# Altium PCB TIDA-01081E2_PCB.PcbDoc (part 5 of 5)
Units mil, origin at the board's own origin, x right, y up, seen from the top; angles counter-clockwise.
Board outline 8611.33 x 3169.64 mil, 4 copper layers (Top Layer, VCC, GND, Bottom Layer), stack 61.6 mil thick; 411 components, 187 nets, 1087 pads, 1987 vias.
Unrouted connection lines stored in the file: 7.
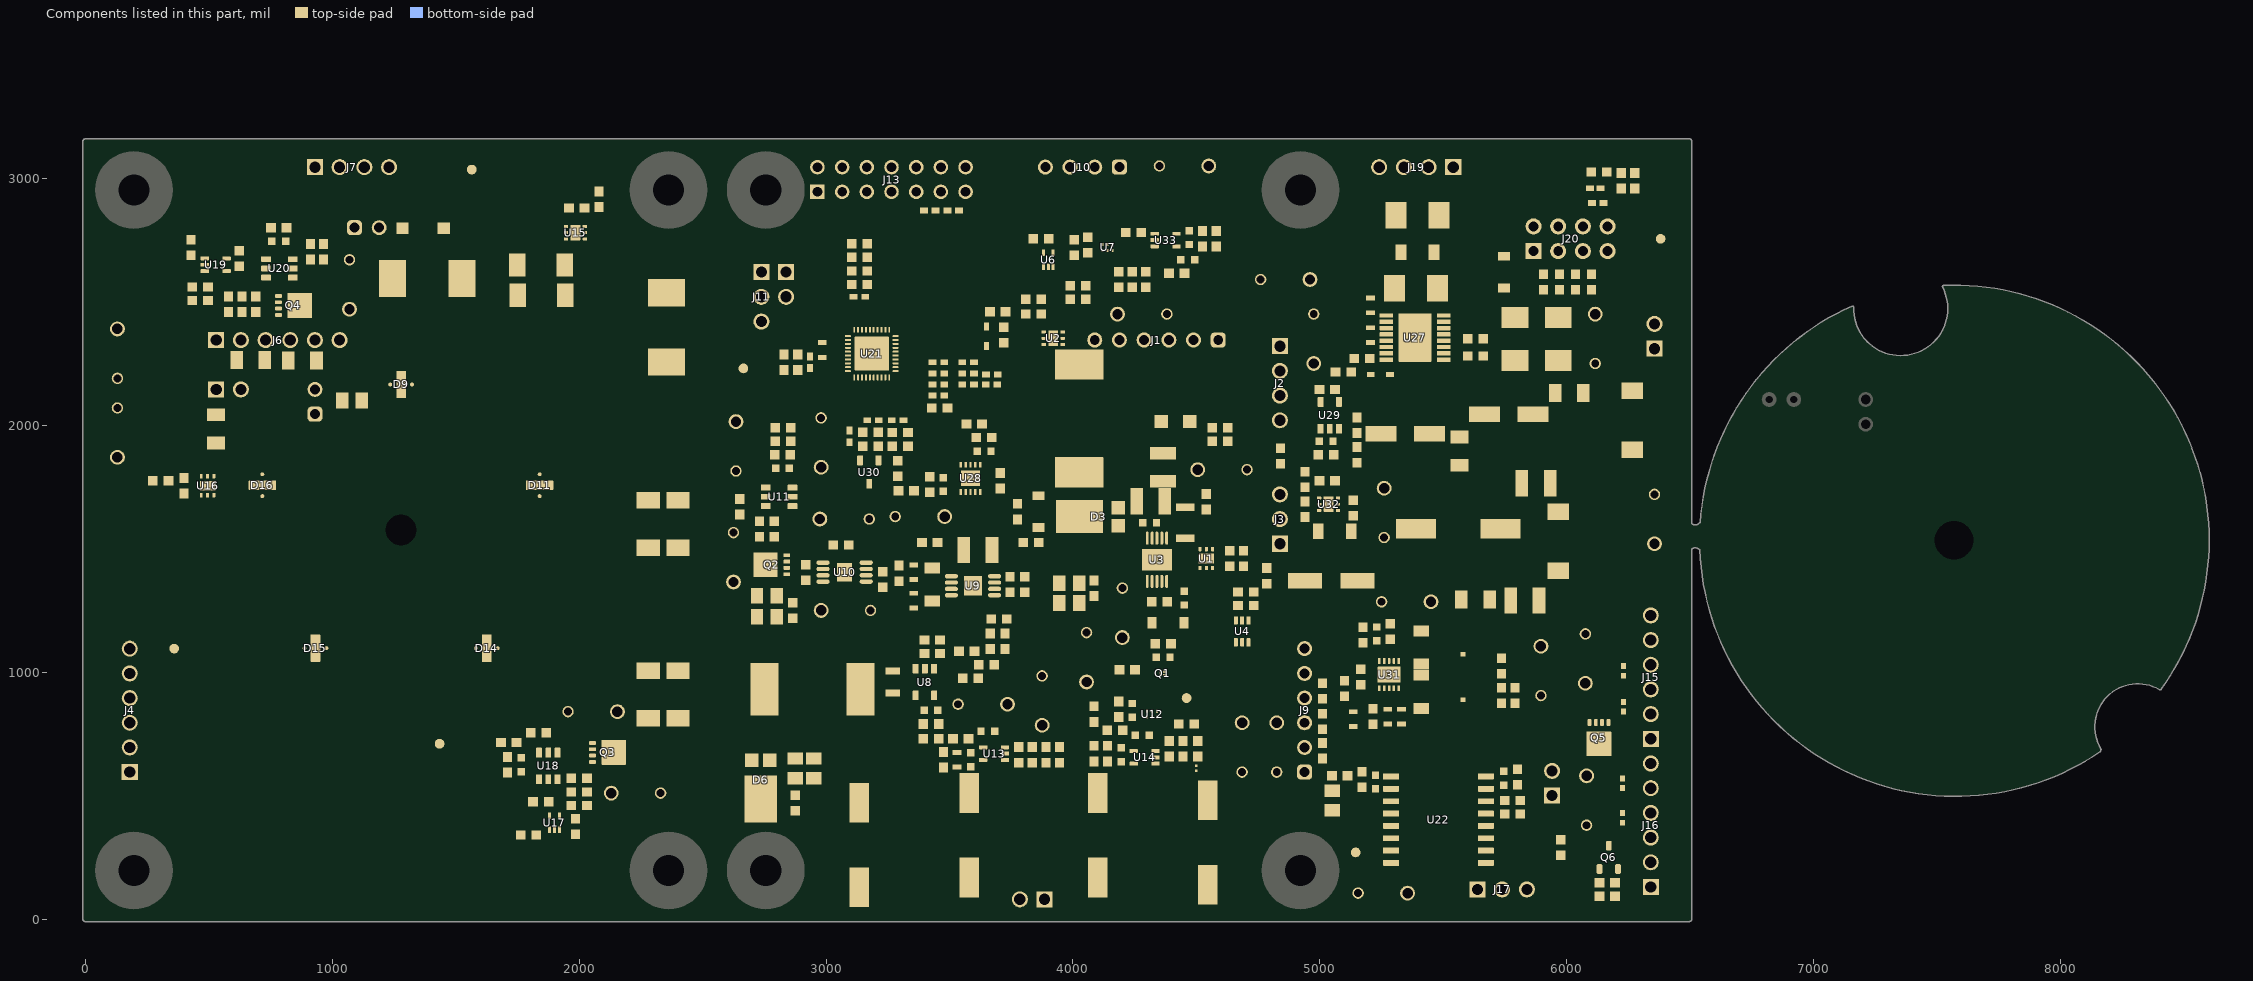
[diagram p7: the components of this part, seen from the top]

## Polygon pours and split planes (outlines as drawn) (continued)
+5V0 on Top Layer "TOP_LAYER_+5V0_P474" (solid, remove dead copper, pour order 474): 690,2850 785,2850 785,2775 690,2775
GND on Top Layer "TOP_LAYER_GND_P476" (solid, remove dead copper, pour order 476): 4221.3,2580 4315,2580 4315,2490 4220,2490
GND on Top Layer "TOP_LAYER_GND_P478" (solid, remove dead copper, pour order 478): 795,2860 795,2780 868.16,2780 875,2786.84 875,2860
+5V0 on Top Layer "TOP_LAYER_+5V0_P480" (solid, remove dead copper, pour order 480): 580,2720 580,2785 670,2785 670,2720
GND_ISO on Top Layer "TOP_LAYER_GND_ISO_P482" (solid, remove dead copper, pour order 482): 6110,775 6110,840 6180,840 6180,775
NetC73_1 on Top Layer "TOP_LAYER_NETC73_1_P484" (solid, remove dead copper, pour order 484): 5720,2665 5805,2665 5805,2765 5720,2765
NetD9_1 on Top Layer "TOP_LAYER_NETD9_1_P486" (solid, remove dead copper, pour order 486): 1160,2140 1160,1920 1050,1920 1050,2120 1070,2140
BUCK_VOUT on VCC "VCC_BUCK_VOUT_P428" (solid, remove dead copper, pour order 428): 4325,2150 4324.8,2150.2 4324.8,2398.9 3773.9,2398.9 3769.09,2394.09 3769.09,2150
NetQ3_5 on VCC "VCC_NETQ3_5_P356" (solid, remove dead copper, pour order 356): 2080,780 2080,560 2530,560 2530,900 2210,900 2210,780
NetR133_1 on VCC "VCC_NETR133_1_P350" (solid, remove dead copper, pour order 350): 2210,900 2530,900 2530,1600 2210,1600
NetD10_1 on VCC "VCC_NETD10_1_P344" (solid, remove dead copper, pour order 344): 2209,2375 2209,1601 2210,1600 2530,1600 2530,2375
NetD10_2 on VCC "VCC_NETD10_2_P334" (solid, remove dead copper, pour order 334): 1850,2375 2530,2375 2530,3100 1850,3100
NetD7_1 on VCC "VCC_NETD7_1_P326" (solid, remove dead copper, pour order 326): 1285,2375 1850,2375 1850,3100 1285,3100 1285,2375
NetC95_1 on VCC "VCC_NETC95_1_P316" (solid, remove dead copper, pour order 316): 979,2160.2 1168.8,2160.2 1170,2850 990,2850 990,2560 790,2560 790,2220.8 789.2,2220 979,2220
NetD9_1 on VCC "VCC_NETD9_1_P235" (solid, remove dead copper, pour order 235): 1179,2245 1249.79,2245 1254,2240.79 1254,1875 1179,1875 1179,2150
NetD9_2 on VCC "VCC_NETD9_2_P239" (solid, remove dead copper, pour order 239): 1789,1790 1894,1790 1894,1945 2090,1945 ccw(c2090,2064) 2209,2064 2209,2296 ccw(c2130,2296) 2130,2375 1255,2375 ccw(c1255,2304) 1184,2304 1184,1945 1184,1916 ccw(c1280,1916) 1280,1820 1384,1820 1384,1945 1789,1945
NetD11_2 on VCC "VCC_NETD11_2_P245" (solid, remove dead copper, pour order 245): 1659,1045 1857.83,1045 1859,1043.83 1859,861 ccw(c1925,861) 1925,795 2140,795 ccw(c2140,864) 2209,864 2209,1866 ccw(c2130,1866) 2130,1945 1394,1945 1394,1821.83 1550,1520 1789,1520 1859,1520 1859,1150.17 1659.17,1150.17
NetD14_2 on VCC "VCC_NETD14_2_P247" (solid, remove dead copper, pour order 247): 1859,1520 1859,795 1178.81,795 1178.81,895.45 1178.81,1043.83 970.17,1043.83 964,1050 964,1150 1178.64,1150 1178.81,1320 1430,1345 1548.64,1520
NetD15_2 on VCC "VCC_NETD15_2_P252" (solid, remove dead copper, pour order 252): 641,1730.41 789.79,1730.41 789.79,1520.41 813.57,1520.41 871,1520.41 951,1520.41 1025,1520.41 1178.81,1325.6 1178.81,1189.81 1178.81,795 479,795 479,1520.41 636,1520.41 638.21,1522.63 638.21,1730.41
NetD16_2 on VCC "VCC_NETD16_2_P256" (solid, remove dead copper, pour order 256): 479,1995 1174,1995 1174,1825 1050,1710 1019,1525 479,1525
NetD6_1 on VCC "VCC_NETD6_1_P370" (solid, remove dead copper, pour order 370): 2590,1491.53 2820,1491.53 2820,485 2590,485
+5V0 on VCC "VCC_+5V0_P362" (solid, remove dead copper, pour order 362): 1285,3100 1285,2400 465,2400 465,780 2530,780 2530,310 1010,310 63.69,310 50.85,322.83 50,323.69 50,3100
NetC4_1 on VCC "VCC_NETC4_1_P416" (solid, remove dead copper, pour order 416): 3920,1325 3920,1195 3930,1185 4462.35,1185 4482.35,1205 4482.35,1389.03 4462.35,1409.03 4307.07,1409.03 4295,1396.96 4295,1345 4285,1335 3930,1335
NetC4_1 on VCC "VCC_NETC4_1_P456" (solid, remove dead copper, pour order 456): 3924.71,1851.04 3926.88,1853.21 4120.26,1853.21 4120.26,1570.26 4060,1510 4060,1411.5 3903.5,1411.5 3900,1415 3900,1807.07
BOOST_VOUT/BUCK_VIN on VCC "VCC_BOOST_VOUT/BUCK_VIN_P472" (solid, remove dead copper, pour order 472): 4420,1830 4480,1830 4480,1700 4420,1700
GND_ISO on GND "GND_GND_ISO_P426" (solid, remove dead copper, pour order 426): 5600,50 5605,55 5605,560 5700,655 5975,655 6061.75,741.75 6061.75,1166.75 6175,1280 6440,1280 6440,50
GND on GND "GND_GND_P374" (solid, remove dead copper, pour order 374): 5150,2230 5756.5,2230 5756.5,2350 6446.46,2350 6446.46,1430 5865,1430 5865,798.63 5435,798.63 5435,50 2590,50 2590,3100 5150,3100
NetQ3_5 on GND "GND_NETQ3_5_P358" (solid, remove dead copper, pour order 358): 2080,780 2080,560 2530,560 2530,900 2210,900 2210,780
NetR133_1 on GND "GND_NETR133_1_P352" (solid, remove dead copper, pour order 352): 2210,900 2530,900 2530,1600 2210,1600
NetD10_1 on GND "GND_NETD10_1_P346" (solid, remove dead copper, pour order 346): 2209,2375 2209,1601 2210,1600 2530,1600 2530,2375
NetD10_2 on GND "GND_NETD10_2_P336" (solid, remove dead copper, pour order 336): 1850,2375 2530,2375 2530,3100 1850,3100
NetD7_1 on GND "GND_NETD7_1_P328" (solid, remove dead copper, pour order 328): 1285,2375 1850,2375 1850,3100 1285,3100 1285,2375
NetC95_1 on GND "GND_NETC95_1_P320" (solid, remove dead copper, pour order 320): 979,2160.2 1170,2160.2 1170,2850 990,2850 990,2560 790,2560 790,2220.8 789.2,2220 979,2220
NetD9_1 on GND "GND_NETD9_1_P237" (solid, remove dead copper, pour order 237): 1179,2245 1249.79,2245 1254,2240.79 1254,1875 1179,1875 1179,2150
NetD9_2 on GND "GND_NETD9_2_P241" (solid, remove dead copper, pour order 241): 1789,1790 1894,1790 1894,1945 2100,1945 ccw(c2100,2054) 2209,2054 2209,2248 ccw(c2150.5,2242.5) 2145,2301 1240,2301 ccw(c1238.5,2246.5) 1184,2248 1184,1945 1184,1820 1384,1820 1384,1945 1789,1945
NetD11_2 on GND "GND_NETD11_2_P244" (solid, remove dead copper, pour order 244): 1659,1045 1857.83,1045 1859,1043.83 1859,861 ccw(c1925,861) 1925,795 2140,795 ccw(c2140,864) 2209,864 2209,1866 ccw(c2130,1866) 2130,1945 1394,1945 1394,1820 1540,1520 1789,1520 1859,1520 1859,1150.17 1659.17,1150.17
NetD14_2 on GND "GND_NETD14_2_P249" (solid, remove dead copper, pour order 249): 1859,1520 1859,795 1178.81,795 1178.81,895.45 1178.81,1043.83 970.17,1043.83 964,1050 964,1150 1178.64,1150 1178.81,1325 1445,1360 1540,1520
NetD15_2 on GND "GND_NETD15_2_P253" (solid, remove dead copper, pour order 253): 641,1730.41 789.79,1730.41 789.79,1520.41 813.57,1520.41 871,1520.41 951,1520.41 1025,1522.63 1178.81,1325 1178.81,1189.81 1178.81,795 479,795 479,1520.41 636,1520.41 638.21,1522.63 638.21,1730.41
NetD16_2 on GND "GND_NETD16_2_P257" (solid, remove dead copper, pour order 257): 479,1995 1174,1995 1174,1825 1050,1715 1015,1525 479,1525
NetC73_1 on GND "GND_NETC73_1_P368" (solid, remove dead copper, pour order 368): 5265,2230 6446.46,2230 6446.46,3100 5150,3100 5150,2230
NetD6_1 on GND "GND_NETD6_1_P372" (solid, remove dead copper, pour order 372): 2590,1485 2820,1485 2820,485 2590,485
NetC4_1 on GND "GND_NETC4_1_P458" (solid, remove dead copper, pour order 458): 3924.71,1851.04 3926.88,1853.21 4120.26,1853.21 4120.26,1570.26 4060,1510 4060,1411.5 3903.5,1411.5 3900,1415 3900,1807.07
GND on GND "GND_GND_P468" (solid, remove dead copper, pour order 468): 1175,300 1175,780 468.91,780 465,783.91 468.92,2244.17 789.2,2244.17 789.2,2405.2 1280,2405.2 1280,3095 55,3095 50,3100 50,300 615,300
GND on GND "GND_GND_P470" (solid, remove dead copper, pour order 470): 1525,780 2060,780 2060,550 2530,550 2530,310 1520,310
NetC73_1 on Bottom Layer "BOTTOM_LAYER_NETC73_1_P432" (solid, remove dead copper, pour order 432): 5151.67,2780 5600,2780 5600,2690 5739.66,2690 5739.66,2231.67 5151.67,2230 5150,2231.67
NetQ3_5 on Bottom Layer "BOTTOM_LAYER_NETQ3_5_P360" (solid, remove dead copper, pour order 360): 2080,780 2080,560 2530,560 2530,900 2210,900 2210,780
NetR133_1 on Bottom Layer "BOTTOM_LAYER_NETR133_1_P354" (solid, remove dead copper, pour order 354): 2210,900 2530,900 2530,1600 2210,1600
NetD10_1 on Bottom Layer "BOTTOM_LAYER_NETD10_1_P348" (solid, remove dead copper, pour order 348): 2209,2375 2209,1601 2210,1600 2530,1600 2530,2375
NetD10_2 on Bottom Layer "BOTTOM_LAYER_NETD10_2_P338" (solid, remove dead copper, pour order 338): 1850,2375 2530,2375 2530,3100 1850,3100
NetD7_1 on Bottom Layer "BOTTOM_LAYER_NETD7_1_P330" (solid, remove dead copper, pour order 330): 1285,2375 1850,2375 1850,3100 1285,3100 1285,2375
NetC95_1 on Bottom Layer "BOTTOM_LAYER_NETC95_1_P322" (solid, remove dead copper, pour order 322): 979,2160.2 1168.8,2160.2 1170,2850 990,2850 990,2560 790,2560 790,2220.8 789.2,2220 979,2220
NetD9_1 on Bottom Layer "BOTTOM_LAYER_NETD9_1_P238" (solid, remove dead copper, pour order 238): 1179,2245 1249.79,2245 1254,2240.79 1254,1995 1179,1995 1179,2150
NetD9_2 on Bottom Layer "BOTTOM_LAYER_NETD9_2_P242" (solid, remove dead copper, pour order 242): 1789,1790 1894,1790 1894,1945 2095,1945 ccw(c2095,2059) 2209,2059 2209,2316 ccw(c2150,2316) 2150,2375 1245,2375 ccw(c1245,2314) 1184,2314 1184,1945 1184,1820 1384,1820 1384,1945 1789,1945
NetD11_2 on Bottom Layer "BOTTOM_LAYER_NETD11_2_P246" (solid, remove dead copper, pour order 246): 1659,1045 1857.83,1045 1859,1043.83 1859,861 ccw(c1925,861) 1925,795 2140,795 ccw(c2140,864) 2209,864 2209,1866 ccw(c2130,1866) 2130,1945 1394,1945 1394,1820 1550,1520 1789,1520 1859,1520 1859,1150.17 1659.17,1150.17
NetD14_2 on Bottom Layer "BOTTOM_LAYER_NETD14_2_P250" (solid, remove dead copper, pour order 250): 1859,1520 1859,795 1178.81,795 1178.81,895.45 1178.81,1043.83 970.17,1043.83 964,1050 964,1150 1178.64,1150 1178.81,1320 1430,1345 1535,1520
NetD15_2 on Bottom Layer "BOTTOM_LAYER_NETD15_2_P254" (solid, remove dead copper, pour order 254): 641,1730.41 789.79,1730.41 789.79,1520.41 813.57,1520.41 871,1520.41 1025,1520.41 1178.81,1325 1178.81,1189.81 1178.81,795 479,795 479,1520.41 636,1520.41 638.21,1522.63 638.21,1730.41
NetD16_2 on Bottom Layer "BOTTOM_LAYER_NETD16_2_P258" (solid, remove dead copper, pour order 258): 479,1995 1174,1995 1174,1820 1055,1715 1020,1525 479,1525
GND on Bottom Layer "BOTTOM_LAYER_GND_P378" (solid, remove dead copper, pour order 378): 5390,2780 5600,2780 5600,3100 5600,2690 6025,2690 6025,2490 6025,2175 5738.75,2175 5738.75,2405 5708.5,2405 5480,2633.5 5458.5,2655 5390,2655
NetD6_1 on Bottom Layer "BOTTOM_LAYER_NETD6_1_P366" (solid, remove dead copper, pour order 366): 2590,1485 2820,1485 2820,485 2590,485
GND on Bottom Layer "BOTTOM_LAYER_GND_P452" (solid, remove dead copper, pour order 452): 4296.04,1396.96 4526.96,1396.96 4540,1410 4545,1415 4545,1880 4275,1880 4255,1860 4125,1730 4125,1538.9 4125,1340 4130,1335 4135,1340 4280,1340 4280,1343.41 4296.04,1359.46
NetC4_1 on Bottom Layer "BOTTOM_LAYER_NETC4_1_P460" (solid, remove dead copper, pour order 460): 3924.71,1851.04 3926.88,1853.21 4120.26,1853.21 4120.26,1570.26 4060,1510 4060,1411.5 3903.5,1411.5 3900,1415 3900,1807.07

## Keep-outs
VCC:
  lines w0: 479,1813.42 563.42,1813.42 ; 480,1700 575,1700 ; 3870,2273.97 3870,2400 ; 3978.39,2368.33 3978.39,2336.61 3980,2335
GND:
  lines w0: 480,1700 570,1700 ; 485,1815 570,1815 ; 3888.72,1180 4012.99,1180 4025.99,1193 4472,1193 4480,1185 4480,1420 4475,1425 4430,1425 4404.54,1399.54 4370,1399.54 4334.54,1399.54 4245,1310 4195,1310 ; 3900,2300 3900,2370 ; 3940,2300 3940,2370 ; 3946.2,2391.17 3871.17,2391.17 3870,2390 3870,2285 3970,2285 ; 3978.39,2368.33 3978.39,2336.61 3980,2335 ; 4115,2030 4115,1441.1 4144.6,1411.5 4144.6,1320.4 4155,1310 4198.88,1310 ; 4485,1498.39 4579.72,1498.39 4581.73,1496.38 4581.73,1420 ; 4498.66,1420 4581.73,1420 ; 4581.73,1420 4581.73,1420 ; 3890,1075 4165,1075 4345,895 4735,895 4845,1005 4845,1385 4590,1640 4280,1640 4275,1645 4275,1717.24 4285.26,1727.5 4292.5,1727.5 4412.5,1727.5 4752.5,1727.5 4820,1795 4915,1890 4915,2425 4845,2495 4635,2495 4360,2495 4355,2495 4335,2475 4335,2250.2 3890,1805.2 3890,1075
Bottom Layer:
  lines w0: 480,1700 565,1700 ; 490,1813.42 563.42,1813.42
Keep-Out Layer:
  circle w10: c1279,1575 r6.5
  circle w10: c1279,1575 r275.59
  text ".Layer_Name" at 577,-858.49 h60

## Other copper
Top Layer:
  text ".Layer_Name" at 577,-858.49 h60
VCC:
  text ".Layer_Name" at 577,-858.49 h60
GND:
  text ".Layer_Name" at 577,-858.49 h60
Bottom Layer:
  text ".Layer_Name" at 577,-858.49 h60

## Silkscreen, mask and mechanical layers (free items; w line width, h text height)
Top Overlay:
  rectangle: 1115,200 1415,300
  lines w10: 660,2570 660,2595 693.11,2628.11 693.11,2761.89 665,2790 665,2890 ; 3235,1740 3243.9,1748.9 3243.9,1750 3247.48,1750 3261.46,1763.98 ; 3490,1535 3495,1535 3550,1590 3550,1595 ; 4230,1565 4230,1605 4245,1620 4245,1635 ; 4340,780 4380,825 ; 4865,870 4885,870 ; 4890,865 4910,845 4970,845 ; 5115,1515 5125,1505 5175,1505 ; 5649.98,3032.32 5729.94,3032.32 ; 5664.97,3017.3 5714.95,3017.3 ; 5679.96,3002.28 5699.95,3002.28 ; 5688.29,2987.25 5693.29,2987.25 ; 5689.96,3032.32 5689.96,3072.39 ; 6770,2050 6940,2050 6970,2080 6970,2150 6770,2150 6770,2050 ; 7160,1980 7160,2150 7260,2150 7260,1950 7190,1950 7160,1980 ; 7317.72,732.6 7829.53,732.6 7829.53,1086.93 7317.72,1086.93 7317.72,732.6
  text "+" at 5087.66,2974.66 h200
  text "Caution:  / Hot Surface" at 3800,2580 h78.74 r90
  text "J8" at 6850,2170 h72.83
  text "J5" at 7180,2170 h72.83
  text "Warning: Possibly hazardous /  optical radiation emitted /   from this product" at 7061.81,1677.48 h72.83
  text "Caution:  / Hot Surface" at 70,1350 h78.74
  text "TIDA-01081" at 8242.91,1323.15 h108.27 r90
  text "Warning: Possibly hazardous /  optical radiation emitted /   from this product" at 755,1290 h72.83
  text "Place UL Sign +  / UL Class +  / E Number of used PCB material" at 7120.87,850.71 h72.83
  text "'.PRJ_Number'.PCB_Rev-" at 425,210 h108.27
  text ".Layer_Name" at 577,-858.49 h60
Bottom Overlay:
  lines w10: 4590.02,2220 4669.98,2220 ; 4605.01,2204.98 4654.99,2204.98 ; 4620,2189.95 4640,2189.95 ; 4626.67,2174.93 4631.67,2174.93 ; 4630,2220 4630,2260.06 ; 5649.98,3040 5729.94,3040 ; 5664.97,3024.98 5714.95,3024.98 ; 5679.96,3009.95 5699.95,3009.95 ; 5686.63,2994.93 5691.62,2994.93 ; 5689.96,3040 5689.96,3080.06 ; 4400,455 4950,455 4950,530 4880,530 4880,860 4760,860 4760,530 4400,530 4400,455
  text "+" at 5059.66,2992.66 h200 r270
  text "VIN: 8 - 36 V / 1.5 A" at 5735,2915 h72.83
  text "+" at 4119.66,2187.66 h200 r270
  text "24 V / 2.4 A" at 4565,2140 h72.83
  text "38 to 49 V / 1.8 A" at 4930,470 h72.83
  text "Warning: Possibly hazardous /  optical radiation emitted /   from this product" at 1757.38,448.67 h72.83
  text ".Layer_Name" at 577,-858.49 h60
Top Paste:
  text ".Layer_Name" at 577,-858.49 h60
Bottom Paste:
  text ".Layer_Name" at 577,-858.49 h60
Top Solder:
  rectangle: 6530,490 8610,2570
  text ".Layer_Name" at 577,-858.49 h60
  text ".Layer_Name" at 577,-858.49 h60
Bottom Solder:
  rectangle: 1597,1555 2070,2028
  rectangle: 1390,861 1862,1333
  rectangle: 481,1521 963,1994
  rectangle: 1043,1929 1515,2402
  rectangle: 696,861 1168,1333
  rectangle: 6530,490 8610,2570
  text ".Layer_Name" at 577,-858.49 h60
Drill Guide:
  text ".Layer_Name" at 577,-858.49 h60
M1 Board Outline:
  lines w10: 6540,1500 ccw(c6520,1480) 6500,1500 6500,3.94 6496.06,0 0,0 0,3149.61 6496.06,3149.61 6500,3145.67 6500,1600 ccw(c6520,1620) 6540,1600 ; 7419.56,513.99 ccw(c7568.3,1534.09) 7543.45,503.51 ; 8156.42,681.56 cw(c7574.8,1534.09) 7156.58,2477.58 ccw(c7352.06,2472.52) 7526.31,2561.23 cw(c7568.3,1534.09) 8402.95,933.97 ; 8158.3,686.89 cw(c8312.24,778.71) 8402.66,933.47
  lines w20: 6496.06,0 0,0 0,3149.61 6496.06,3149.61
  text ".Layer_Name" at 577,-858.49 h60
M2 Board Dimensions:
  rectangle: 125,-400 500,-275
  rectangle: 0,-275 125,-150
  lines w7: 0,-275 1000,-275 ; 125,-400 125,-150 ; 250,-400 250,-150 ; 500,-400 500,-150 ; 750,-400 750,-150 ; 0,-400 0,-150 1000,-150 1000,-400 0,-400
  lines w10: 6500,1480 6500,1610
  text ".Layer_Name" at 577,-858.49 h60
M3 3D STEP Top:
  text ".Layer_Name" at 577,-858.49 h60
M4 3D STEP Bottom:
  text ".Layer_Name" at 577,-858.49 h60
M5 Assembly Top:
  lines w10: -292,-930.17 6308,-930.17 ; -292,-726.83 6310,-726.83 ; -292,-523.5 -292,-1133.5 3713,-1133.5 6310,-1133.5 6310,-523.5 -291.5,-523.5 -291.5,-1133.5 1284,-1133.5 ; 2173,-1133.5 2173,-523.5 ; 3440,-726.83 3440,-523.5 ; 4280,-726.83 4280,-523.5 ; 4902,-1140 4902,-937.17
  text "COMPONENTS MARKED 'DNP' SHOULD NOT BE POPULATED." at 1153.5,-318.5 h60
  text "ASSEMBLY VARIANT:" at 1153,-434 h60
  text ".VariantName" at 2189,-434 h60
  text "PCB VIEWED FROM TOP SIDE" at -228.5,-655.67 h60
  text "BOARD #:" at 2248,-655.67 h60
  text ".PRJ_Number" at 2793.5,-655.67 h60
  text "REV:" at 3638,-655.67 h60
  text ".PCB_Rev" at 3929.5,-655.67 h60
  text "SVN REV:" at 4476,-655.67 h60
  text ".VersionControl_RevNumber" at 4982,-655.67 h60
  text "TID #:" at 2248,-859 h60
  text ".TID" at 2793.5,-859 h60
  text "PLOT NAME =" at -228.5,-1064.34 h60
  text ".plot_File_Name" at 577,-1064.34 h60
  text "GENERATED    :" at 2250,-1064.34 h60
  text ".Print_Date" at 3119.5,-1064.34 h60
  text ".Print_Time" at 3848.5,-1064.34 h60
  text "TEXAS INSTRUMENTS" at 5113,-1064.34 h60
M6 Assembly Bottom:
  lines w10: -292.5,-727.33 6309.5,-727.33 ; -290.5,-930.67 6309.5,-930.67 ; 1115.5,-1140.5 1115.5,-937.67 ; 1737.5,-727.33 1737.5,-524 ; 2577.5,-727.33 2577.5,-524 ; 3844.5,-1134 3844.5,-524 ; 4733.5,-1134 6309,-1134 6309,-524 -292.5,-524 -292.5,-1134 2304.5,-1134 6309.5,-1134 6309.5,-524
  text "COMPONENTS MARKED 'DNP' SHOULD NOT BE POPULATED." at 6102,-318 h60
  text ".VariantName" at 5058,-434 h60
  text "ASSEMBLY VARIANT:" at 6097,-434 h60
  text ".VersionControl_RevNumber" at 1035.5,-656.17 h60
  text "SVN REV:" at 1541.5,-656.17 h60
  text ".PCB_Rev" at 2088,-656.17 h60
  text "REV:" at 2379.5,-656.17 h60
  text ".PRJ_Number" at 3224,-656.17 h60
  text "BOARD #:" at 3769.5,-656.17 h60
  text "PCB VIEWED FROM BOTTOM SIDE" at 6246,-656.17 h60
  text ".TID" at 3224,-859.5 h60
  text "TID #:" at 3769.5,-859.5 h60
  text "TEXAS INSTRUMENTS" at 904.5,-1064.84 h60
  text ".Print_Time" at 2169,-1064.84 h60
  text ".Print_Date" at 2898,-1064.84 h60
  text "GENERATED    :" at 3767.5,-1064.84 h60
  text ".plot_File_Name" at 5440.5,-1064.84 h60
  text "PLOT NAME =" at 6246,-1064.84 h60
M9 Title Sheet:
  drawing of 57 lines, arcs and shapes, not listed
  text "1" at 739.84,8036.5 h70
  text "2" at 3235.5,8036.5 h70
  text "3" at 5724.84,8036.5 h70
  text "4" at 8231.51,8036.5 h70
  text "5" at 10730.5,8036.5 h70
  text "6" at 13235.5,8036.5 h70
  text "A" at -416.5,6893.5 h70
  text "A" at 14383.5,6893.5 h70
  text "B" at -416.5,4513.5 h70
  text "B" at 14383.5,4513.5 h70
  text "C" at -416.5,2138.5 h70
  text "C" at 14383.5,2138.5 h70
  text "PROJECT TITLE:" at 11343.5,277.5 h45
  text ".PRJ_Title" at 11393.5,144.17 h70
  text "DESIGNED FOR:" at 11343.5,-23.5 h45
  text ".PRJ_Customer" at 11393.5,-163.5 h70
  text "D" at -416.5,-231.5 h70
  text "D" at 14383.5,-231.5 h70
  text "FILE NAME:" at 11343.5,-323.5 h45
  text ".PCB_File_Name_No_Path" at 11393.5,-443.5 h70
  text "Texas Instruments (TI) and/or its licensors do not warrant the accuracy or completeness of this specification" at 6374,-605.34 h45
  text "ENGINEER:" at 11343.5,-613.5 h45
  text "LAYOUT BY:" at 12848.5,-613.5 h45
  text "or any information contained therein. TI and/or its licensors do not warrant that this design will meet" at 6329.01,-718 h45
  text ".PRJ_Engineer" at 11393.5,-768.49 h70
  text ".PCB_Layout" at 12899,-768.49 h70
  text "the specifications, will be suitable for your application or fit for any particular purpose, or will operate in" at 6329.01,-830.67 h45
  text ".Layer_Name" at 577,-858.49 h60
  text "ALTIUM DESIGNER VERSION:" at 12848.5,-923.5 h45
  text "an implementation. TI and/or its licensors do not warrant that the design is production worthy. You should" at 6329.01,-943.33 h45
  text "completely validate and test your design implementation to confirm the system functionality for your application." at 6374,-1056 h45
  text ".print_Scale" at 11393.5,-1056.83 h70
  text ".Application_BuildNumber" at 12899,-1056.83 h70
  text "1" at 739.84,-1263.5 h70
  text "2" at 3235.5,-1263.5 h70
  text "3" at 5724.84,-1263.5 h70
  text "4" at 8231.51,-1263.5 h70
  text "5" at 10730.5,-1263.5 h70
  text "6" at 13235.5,-1263.5 h70
M10 Fab Notes:
  drawing of 173 lines, arcs and shapes, not listed
  text "DESIGN INFORMATION" at 12378.02,6201 h60
  text "MIN. TRACK WIDTH:" at 11733.46,6021 h60
  text "6" at 12829.7,6021 h60
  text "MIL" at 12984.46,6021 h60
  text "MIN. CLEARANCE:" at 11733.46,5889 h60
  text "0.1" at 12769.7,5889 h60
  text "mm" at 12984.46,5889 h60
  text "MIN. VIA PAD SIZE:" at 11733.46,5757 h60
  text "24" at 12799.71,5757 h60
  text "MIL" at 12984.46,5757 h60
  text "0.05mm (2MIL)" at 12428.46,5615.29 h60
  text "MINIMUM ANNULAR RING" at 11404.23,5611 h60
  text "EXTERNAL" at 13136.46,5611 h60
  text "PER" at 11604.23,5493 h60
  text "IPC-D-275 CLASS 2 LEVEL C" at 11824.23,5493 h60
  text "MIL, HOLES" at 13312.46,5380.71 h60
  text "+/-" at 12920,5380 h60
  text "+/-" at 13774,5380 h60
  text "REGISTRATION TOLERANCES:" at 11404.23,5375 h60
  text "METAL" at 12604,5375 h60
  text "5" at 13180.2,5375 h60
  text "3" at 14013.2,5375 h60
  text "MIL" at 14129.46,5375 h60
  text "+/-" at 13774,5262 h60
  text "HOLE SIZE TOLERANCE (UNLESS OTHERWISE SPECIFIED):" at 11404.23,5257 h60
  text "3" at 14013.2,5257 h60
  text "MIL" at 14129.46,5257 h60
  text "MATERIAL:" at 11329.46,5047.54 h60
  text "FR-4 High Tg" at 12315.9,4907.21 h60
  text "FR-408" at 11750.46,4898.64 h60
  text "OTHER" at 13238.46,4898.64 h60
  text "X" at 12161,4895 h60
  text "62 MIL (1.6mm) +/-10%" at 12070.56,4735.92 h60
  text "THICKNESS:" at 11404.23,4731.64 h60
  text "X" at 11942.4,4731.64 h60
  text "OTHER" at 13355.46,4731.64 h60
  text "TOLERANCE:" at 11404.23,4573.64 h60
  text "X" at 12243.53,4573.64 h60
  text "ANSI IPC-6012 TYPE 3 CLASS 2" at 12430.48,4573.64 h60
  text "OTHER +/-" at 12430.46,4417.64 h60
  text "BOW & TWIST:" at 11404.23,4260.64 h60
  text "X" at 12243.53,4260.64 h60
  text "ANSI IPC-6012 TYPE 3 CLASS 2" at 12430.48,4260.64 h60
  text "OTHER +/-" at 12430.46,4102.13 h60
  text "DRILLING:" at 11329.46,3963.64 h60
  text "REFERENCE:" at 11404.23,3846.64 h60
  text "X" at 12052.46,3846.64 h60
  text "AS SHOWN" at 12239.46,3846.64 h60
  text "X" at 12953.46,3846.64 h60
  text "NC_DRILL FILES" at 13090.46,3846.64 h60
  text "PTH COPPER THICKNESS:" at 11404.23,3688.64 h60
  text "X" at 12534.46,3688.64 h60
  text "20-30 um" at 12671.46,3688.64 h60
  text "OTHER" at 13388.46,3688.64 h60
  text "BOARD FINISH:" at 11329.46,3529.64 h60
  text "SILKSCREEN:" at 11484.68,3411.64 h60
  text "X" at 12433.46,3411.64 h60
  text "TOP" at 12559.46,3411.64 h60
  text "X" at 12943.46,3411.64 h60
  text "BOTTOM" at 13070.46,3411.64 h60
  text "SILKSCREEN COLOR:" at 11484.68,3244.64 h60
  text "X" at 12432.42,3244.64 h60
  text "WHITE" at 12559.46,3244.64 h60
  text "OTHER" at 13070.46,3244.64 h60
  text "X" at 12563.42,3085.44 h60
  text "GREEN" at 12690.46,3085.44 h60
  text "OTHER" at 13308.46,3085.44 h60
  text "SOLDER RESIST COLOR:" at 11484.68,3074.64 h60
  text "X" at 12563.42,2915.44 h60
  text "MATTE" at 12690.46,2915.44 h60
  text "SEMI-GLOSS" at 13308,2914.8 h60
  text "IMMERSION GOLD (ENIG)" at 12390.46,2726.92 h60
  text "ENEPIG" at 13728,2723.64 h60
  text "SURFACE FINISH:" at 11329.46,2722.64 h60
  text "X" at 12203.51,2722.64 h60
  text "IMM. TIN/SILVER OR EQUIV" at 11659,2565.64 h60
  text "OTHER" at 13090.46,2565.64 h60
  text "ARRAY/PANEL:" at 11329.46,2386.64 h60
  text "CUT AND TRIM PER M1 BOARD OUTLINE" at 12390.46,2382.35 h60
  text "N.C. ROUTE" at 12390.46,2230.64 h60
  text "X" at 13069.46,2230.64 h60
  text "V. SCORE" at 13256.46,2230.64 h60
  text "CERTIFICATION:" at 11329.46,2093.64 h60
  text "MATERIALS AND WORKMANSHIP FOR ALL PCBS" at 12054.46,2093.64 h60
  text "TO MEET OR EXCEED THE REQUIREMENTS OF:" at 12054.46,1995.64 h60
  text "X" at 11680.96,1859.13 h60
  text "ANSI IPC-A-600F CLASS ->" at 11819.96,1859.13 h60
  text "X" at 13459.02,1859.13 h60
  text "2" at 13577.96,1859.14 h60
  text "1" at 13262.96,1857.64 h60
  text "3" at 13931.96,1857.64 h60
  text "X" at 12495.02,1699.64 h60
  text "RoHS" at 12631.96,1699.64 h60
  text "OTHER" at 13276.36,1699.64 h60
  text "PER ORDER" at 13673.42,1699.64 h60
  text "ALL BOARDS MUST MEET OR EXCEED UL94-V0 REQUIREMENTS." at 11357,1534 h60
  text "PCB MUST BEAR THE UL94V-0 UL REGISTERED MATERIAL ID NUMBER" at 11357,1414 h60
  text "ADDITIONAL REQUIREMENTS:" at 11329.46,1240.64 h60
  text "MICROSECTION:" at 11404.23,1125.64 h60
  text "YES" at 12309.96,1125.64 h60
  text "REQUIRED" at 13171.46,969.49 h60
  text "BARE BOARD ELEC. TEST:" at 11404.23,966.64 h60
  text "NONE" at 12709.96,966.64 h60
  text "X" at 13044.46,966.64 h60
  text "PER ORDER" at 13763.46,966.64 h60
  text ".Layer_Name" at 577,-858.49 h60
M11 Gerber Information:
  lines w10: -292,-930.17 6308,-930.17 ; -292,-726.83 6310,-726.83 ; -292,-523.5 -292,-1133.5 3713,-1133.5 6310,-1133.5 6310,-523.5 -291.5,-523.5 -291.5,-1133.5 1284,-1133.5 ; 2173,-1133.5 2173,-523.5 ; 3440,-726.83 3440,-523.5 ; 4280,-726.83 4280,-523.5 ; 4902,-1140 4902,-937.17
  text "ALL ARTWORK VIEWED FROM TOP SIDE" at -228.5,-655.67 h60
  text "BOARD #:" at 2248,-655.67 h60
  text ".PRJ_Number" at 2793.5,-655.67 h60
  text "REV:" at 3638,-655.67 h60
  text ".PCB_Rev" at 3929.5,-655.67 h60
  text "SVN REV:" at 4476,-655.67 h60
  text ".VersionControl_RevNumber" at 4982,-655.67 h60
  text "LAYER NAME =" at -228.5,-858.49 h60
  text "TID #:" at 2248,-859 h60
  text ".TID" at 2793.5,-859 h60
  text "PLOT NAME =" at -228.5,-1064.34 h60
  text ".plot_File_Name" at 577,-1064.34 h60
  text "GENERATED    :" at 2250,-1064.34 h60
  text ".Print_Date" at 3119.5,-1064.34 h60
  text ".Print_Time" at 3848.5,-1064.34 h60
  text "TEXAS INSTRUMENTS" at 5113,-1064.34 h60
M12 Stackup:
  drawing of 295 lines, arcs and shapes, not listed
  text "Layer" at 9797.84,7830 h60
  text "Name" at 10207.76,7830 h60
  text "Material" at 11137.5,7830 h60
  text "Thickness" at 11997.27,7830 h60
  text "Constant" at 12647.1,7830 h60
  text "Board Layer Stack" at 13216.96,7830 h60
  text "1" at 9797.84,7710 h60
  text "Top Overlay" at 10207.76,7710 h60
  text "2" at 9797.84,7590 h60
  text "Top Solder" at 10207.76,7590 h60
  text "Solder Resist" at 11137.5,7590 h60
  text "0.40mil" at 11997.27,7590 h60
  text "3.5" at 12647.1,7590 h60
  text "3" at 9797.84,7470 h60
  text "Top Layer" at 10207.76,7470 h60
  text "Copper" at 11137.5,7470 h60
  text "1.40mil" at 11997.27,7470 h60
  text "4" at 9797.84,7350 h60
  text "Dielectric 1" at 10207.76,7350 h60
  text "FR-4" at 11137.5,7350 h60
  text "8.00mil" at 11997.27,7350 h60
  text "4.2" at 12647.1,7350 h60
  text "5" at 9797.84,7230 h60
  text "VCC" at 10207.76,7230 h60
  text "Copper" at 11137.5,7230 h60
  text "1.40mil" at 11997.27,7230 h60
  text "6" at 9797.84,7110 h60
  text "Dielectric 2" at 10207.76,7110 h60
  text "FR-4" at 11137.5,7110 h60
  text "40.00mil" at 11997.27,7110 h60
  text "4.2" at 12647.1,7110 h60
  text "7" at 9797.84,6990 h60
  text "GND" at 10207.76,6990 h60
  text "Copper" at 11137.5,6990 h60
  text "1.40mil" at 11997.27,6990 h60
  text "8" at 9797.84,6870 h60
  text "Dielectric 3" at 10207.76,6870 h60
  text "FR-4" at 11137.5,6870 h60
  text "8.00mil" at 11997.27,6870 h60
  text "4.2" at 12647.1,6870 h60
  text "9" at 9797.84,6750 h60
  text "Bottom Layer" at 10207.76,6750 h60
  text "Copper" at 11137.5,6750 h60
  text "1.40mil" at 11997.27,6750 h60
  text "10" at 9797.84,6630 h60
  text "Bottom Solder" at 10207.76,6630 h60
  text "Solder Resist" at 11137.5,6630 h60
  text "0.40mil" at 11997.27,6630 h60
  text "3.5" at 12647.1,6630 h60
  text "11" at 9797.84,6510 h60
  text "Bottom Overlay" at 10207.76,6510 h60
  text ".Layer_Name" at 577,-858.49 h60
M13 Component Bodies Top:
  text ".Layer_Name" at 577,-858.49 h60
M14 Component Bodies Bottom:
  text ".Layer_Name" at 577,-858.49 h60
M15 Courtyards Top:
  text ".Layer_Name" at 577,-858.49 h60
M16 Courtyards Bottom:
  text ".Layer_Name" at 577,-858.49 h60
Drill Drawing:
  circle w10: c5268.72,5033.08 r27.63
  circle w10: c5268.72,4908.76 r16.58
  circle w10: c5268.72,4908.76 r27.63
  lines w10: 5241.09,4687.75 5296.34,4687.75 5268.72,4632.5 5241.09,4687.75 ; 5241.09,4784.44 5268.72,4756.82 5296.34,4784.44 5268.72,4812.07 5241.09,4784.44 ; 5241.09,5185.03 5296.34,5185.03 5268.72,5129.78 5241.09,5185.03 ; 5241.09,5267.91 5254.9,5267.91 5254.9,5254.1 5282.53,5254.1 5282.53,5267.91 5296.34,5267.91 5296.34,5295.54 5282.53,5295.54 5282.53,5309.35 5254.9,5309.35 5254.9,5295.54 5241.09,5295.54 5241.09,5267.91 ; 5241.09,5392.23 5254.9,5392.23 5268.72,5378.42 5282.53,5392.23 5296.34,5392.23 5282.53,5406.04 5296.34,5419.86 5282.53,5419.86 5268.72,5433.67 5254.9,5419.86 5241.09,5419.86 5254.9,5406.04 5241.09,5392.23 ; 5241.09,5502.74 5296.34,5502.74 5296.34,5557.99 5241.09,5557.99 5241.09,5502.74 ; 5241.09,5640.87 5254.9,5640.87 5254.9,5627.06 5282.53,5627.06 5282.53,5640.87 5296.34,5640.87 5296.34,5668.5 5282.53,5668.5 5282.53,5682.31 5254.9,5682.31 5254.9,5668.5 5241.09,5668.5 5241.09,5640.87 ; 5241.09,5751.38 5241.09,5765.19 5254.9,5779 5241.09,5792.82 5241.09,5806.63 5254.9,5806.63 5268.72,5792.82 5282.53,5806.63 5296.34,5806.63 5296.34,5792.82 5282.53,5779 5296.34,5765.19 5296.34,5751.38 5282.53,5751.38 5268.72,5765.19 5254.9,5751.38 5241.09,5751.38 ; 5241.09,5875.7 5268.72,5889.51 5296.34,5875.7 5282.53,5903.32 5296.34,5930.95 5268.72,5917.14 5241.09,5930.95 5254.9,5903.32 5241.09,5875.7 ; 5241.09,6000.02 5296.34,6000.02 5296.34,6055.27 5241.09,6055.27 5241.09,6000.02 ; 5241.09,6124.34 5268.72,6138.15 5296.34,6124.34 5282.53,6151.96 5296.34,6179.59 5268.72,6165.78 5241.09,6179.59 5254.9,6151.96 5241.09,6124.34 ; 5252.14,5173.98 5285.29,5173.98 5268.72,5140.83 5252.14,5173.98 ; 5252.14,5273.43 5260.43,5273.43 5260.43,5265.15 5277.01,5265.15 5277.01,5273.43 5285.29,5273.43 5285.29,5290.01 5277.01,5290.01 5277.01,5298.3 5260.43,5298.3 5260.43,5290.01 5252.14,5290.01 5252.14,5273.43 ; 5252.14,5397.75 5260.43,5397.75 5268.72,5389.47 5277.01,5397.75 5285.29,5397.75 5277.01,5406.04 5285.29,5414.33 5277.01,5414.33 5268.72,5422.62 5260.43,5414.33 5252.14,5414.33 5260.43,5406.04 5252.14,5397.75 ; 5252.14,5513.79 5285.29,5513.79 5285.29,5546.94 5252.14,5546.94 5252.14,5513.79 ; 5252.14,5886.75 5268.72,5895.03 5285.29,5886.75 5277.01,5903.32 5285.29,5919.9 5268.72,5911.61 5252.14,5919.9 5260.43,5903.32 5252.14,5886.75
  lines w12: 5191,4595.2 8422.65,4595.2 ; 5191,6335.68 8422.65,6335.68 ; 5528.86,4470.88 5528.86,6460 ; 5861.03,4470.88 5861.03,6460 ; 6497.59,4470.88 6497.59,6460 ; 6756.73,4470.88 6756.73,6460 ; 7131.89,4470.88 7131.89,6460 ; 7856.22,4470.88 7856.22,6460 ; 5191,4470.88 8422.65,4470.88 8422.65,6460 5191,6460 5191,4470.88
  text "Symbol" at 5265.59,6372.98 h72
  text "Quantity" at 5566.16,6372.98 h72
  text "Finished Hole Size" at 5898.33,6372.98 h72
  text "Plated" at 6534.89,6372.98 h72
  text "Hole Type" at 6794.03,6372.98 h72
  text "Drill Layer Pair" at 7169.19,6372.98 h72
  text "Hole Tolerance" at 7893.52,6372.98 h72
  text "1" at 5566.16,6248.66 h60
  text "125.98mil (3.200mm)" at 5898.33,6248.66 h60
  text "NPTH" at 6534.89,6248.66 h60
  text "Round" at 6794.03,6248.66 h60
  text "Top Layer - Bottom Layer" at 7169.19,6248.66 h60
  text "C" at 5240.31,6238.66 h55.25
  text "1" at 5566.16,6124.34 h60
  text "157.48mil (4.000mm)" at 5898.33,6124.34 h60
  text "NPTH" at 6534.89,6124.34 h60
  text "Round" at 6794.03,6124.34 h60
  text "Top Layer - Bottom Layer" at 7169.19,6124.34 h60
  text "66" at 5566.16,6000.02 h60
  text "7.87mil (0.200mm)" at 5898.33,6000.02 h60
  text "PTH" at 6534.89,6000.02 h60
  text "Round" at 6794.03,6000.02 h60
  text "Top Layer - Bottom Layer" at 7169.19,6000.02 h60
  text "1142" at 5566.16,5875.7 h60
  text "12.00mil (0.305mm)" at 5898.33,5875.7 h60
  text "PTH" at 6534.89,5875.7 h60
  text "Round" at 6794.03,5875.7 h60
  text "Top Layer - Bottom Layer" at 7169.19,5875.7 h60
  text "779" at 5566.16,5751.38 h60
  text "20.00mil (0.508mm)" at 5898.33,5751.38 h60
  text "PTH" at 6534.89,5751.38 h60
  text "Round" at 6794.03,5751.38 h60
  text "Top Layer - Bottom Layer" at 7169.19,5751.38 h60
  text "2" at 5566.16,5627.06 h60
  text "30.00mil (0.762mm)" at 5898.33,5627.06 h60
  text "PTH" at 6534.89,5627.06 h60
  text "Round" at 6794.03,5627.06 h60
  text "Top Layer - Bottom Layer" at 7169.19,5627.06 h60
  text "30" at 5566.16,5502.74 h60
  text "32.00mil (0.813mm)" at 5898.33,5502.74 h60
  text "PTH" at 6534.89,5502.74 h60
  text "Round" at 6794.03,5502.74 h60
  text "Top Layer - Bottom Layer" at 7169.19,5502.74 h60
  text "16" at 5566.16,5378.42 h60
  text "39.37mil (1.000mm)" at 5898.33,5378.42 h60
  text "PTH" at 6534.89,5378.42 h60
  text "Round" at 6794.03,5378.42 h60
  text "Top Layer - Bottom Layer" at 7169.19,5378.42 h60
  text "8" at 5566.16,5254.1 h60
  text "40.00mil (1.016mm)" at 5898.33,5254.1 h60
  text "PTH" at 6534.89,5254.1 h60
  text "Round" at 6794.03,5254.1 h60
  text "Top Layer - Bottom Layer" at 7169.19,5254.1 h60
  text "16" at 5566.16,5129.78 h60
  text "40.16mil (1.020mm)" at 5898.33,5129.78 h60
  text "PTH" at 6534.89,5129.78 h60
  text "Round" at 6794.03,5129.78 h60
  text "Top Layer - Bottom Layer" at 7169.19,5129.78 h60
  text "+/-1.97mil" at 7893.52,5129.78 h60
  text "4" at 5566.16,5005.46 h60
  text "40.16mil (1.020mm)" at 5898.33,5005.46 h60
  text "PTH" at 6534.89,5005.46 h60
  text "Round" at 6794.03,5005.46 h60
  text "Top Layer - Bottom Layer" at 7169.19,5005.46 h60
  text "30" at 5566.16,4881.14 h60
  text "42.00mil (1.067mm)" at 5898.33,4881.14 h60
  text "PTH" at 6534.89,4881.14 h60
  text "Round" at 6794.03,4881.14 h60
  text "Top Layer - Bottom Layer" at 7169.19,4881.14 h60
  text "55" at 5566.16,4756.82 h60
  text "45.28mil (1.150mm)" at 5898.33,4756.82 h60
  text "PTH" at 6534.89,4756.82 h60
  text "Round" at 6794.03,4756.82 h60
  text "Top Layer - Bottom Layer" at 7169.19,4756.82 h60
  text "8" at 5566.16,4632.5 h60
  text "125.98mil (3.200mm)" at 5898.33,4632.5 h60
  text "PTH" at 6534.89,4632.5 h60
  text "Round" at 6794.03,4632.5 h60
  text "Top Layer - Bottom Layer" at 7169.19,4632.5 h60
  text "2158 Total" at 5566.16,4508.18 h60
  text ".Layer_Name" at 577,-858.49 h60
M17 Panel:
  lines w10: 2559.06,0 2559.06,3149.61
  text ".Layer_Name" at 577,-858.49 h60
Mechanical 18:
  text ".Layer_Name" at 577,-858.49 h60
Mechanical 19:
  text ".Layer_Name" at 577,-858.49 h60

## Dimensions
0,-400 to 1000,-400 on M2 Board Dimensions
